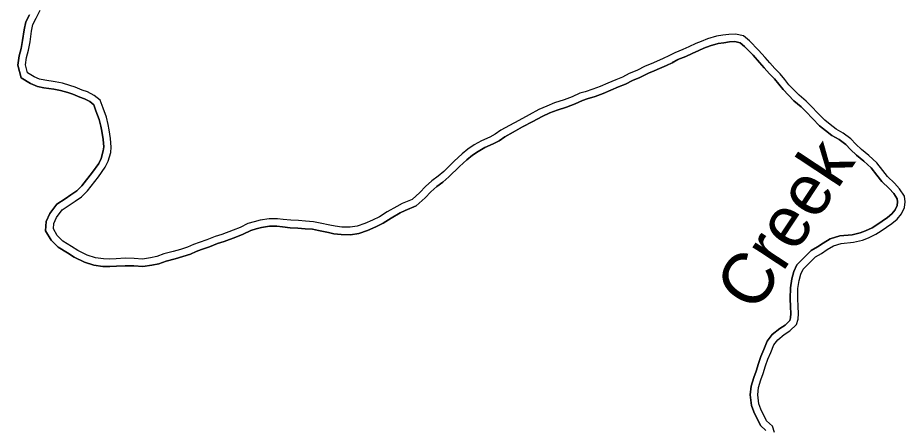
# Model space of a CAD drawing. Extents: x -29.6 to 34, y 0 to 22.
# Drawn here: x -24.699 to -23.161, y 8.694 to 9.402 of the extents above; entities that cross this region are included whole.
import ezdxf

# ---------------------------------------------------------------- set-up
doc = ezdxf.new("R2010")
doc.units = 0
doc.layers.add('GM_X_Major_River', color=7, linetype='Continuous')
doc.layers.add('GM_X_Major_River_Text', color=7, linetype='Continuous')

msp = doc.modelspace()

# ---------------------------------------------------------------- linework, layer by layer
at = {"layer": 'GM_X_Major_River'}
for points in [[(-24.5511, 9.2451), (-24.5561, 9.2589), (-24.5665, 9.2673), (-24.5779, 9.2736), (-24.5871, 9.2764), (-24.5992, 9.2813), (-24.6084, 9.2844), (-24.6215, 9.2883), (-24.634, 9.291), (-24.6517, 9.2934), (-24.6609, 9.2951), (-24.6705, 9.2993), (-24.6819, 9.3063), (-24.6855, 9.3201), (-24.6835, 9.3329), (-24.68, 9.3457), (-24.6776, 9.3603), (-24.6749, 9.3788), (-24.6725, 9.3902), (-24.6669, 9.4013), (-24.6603, 9.4148)], [(-24.5634, 9.2406), (-24.5672, 9.251), (-24.5738, 9.2565), (-24.583, 9.2615), (-24.5914, 9.2641), (-24.6037, 9.2691), (-24.6123, 9.272), (-24.6248, 9.2756), (-24.6362, 9.2781), (-24.6537, 9.2805), (-24.6648, 9.2825), (-24.6766, 9.2877), (-24.6932, 9.2979), (-24.6989, 9.3195), (-24.6963, 9.3357), (-24.6928, 9.3485), (-24.6906, 9.3623), (-24.6878, 9.3811), (-24.685, 9.3946), (-24.6786, 9.4071)], [(-24.6786, 9.4071), (-24.685, 9.3946), (-24.6878, 9.3811), (-24.6906, 9.3623), (-24.6928, 9.3485), (-24.6963, 9.3357), (-24.6989, 9.3195), (-24.6932, 9.2979), (-24.6766, 9.2877), (-24.6648, 9.2825), (-24.6537, 9.2805), (-24.6362, 9.2781), (-24.6248, 9.2756), (-24.6123, 9.272), (-24.6037, 9.2691), (-24.5914, 9.2641), (-24.583, 9.2615), (-24.5738, 9.2565), (-24.5672, 9.251), (-24.5634, 9.2407)], [(-23.3877, 8.6831), (-23.3909, 8.6941), (-23.4016, 8.7032), (-23.4113, 8.7238), (-23.4146, 8.733), (-23.4165, 8.7486), (-23.4151, 8.761), (-23.4113, 8.7745), (-23.4071, 8.7852), (-23.403, 8.7984), (-23.3991, 8.8102), (-23.3939, 8.8219), (-23.3887, 8.8348), (-23.382, 8.8437), (-23.3707, 8.8527), (-23.3609, 8.8591), (-23.3496, 8.8702), (-23.3468, 8.8795), (-23.3462, 8.8894), (-23.3466, 8.9015), (-23.3474, 8.9154), (-23.3472, 8.9328), (-23.3451, 8.9466), (-23.342, 8.9573), (-23.3378, 8.9662), (-23.3164, 8.9877), (-23.3061, 8.9935), (-23.2963, 9.0003), (-23.2857, 9.0068), (-23.2719, 9.0108), (-23.2506, 9.0127), (-23.2354, 9.0164), (-23.2248, 9.0204), (-23.2121, 9.0265), (-23.2029, 9.0323), (-23.1938, 9.0388), (-23.1842, 9.0452), (-23.1751, 9.0528), (-23.1677, 9.0621), (-23.1625, 9.0728), (-23.1611, 9.0827), (-23.1622, 9.0927), (-23.1708, 9.1054), (-23.1797, 9.1149), (-23.1919, 9.1269), (-23.2001, 9.1371), (-23.2105, 9.1505), (-23.224, 9.1629), (-23.2368, 9.1734), (-23.2468, 9.1829), (-23.2554, 9.1921), (-23.2689, 9.2016), (-23.281, 9.2086), (-23.291, 9.2167), (-23.3006, 9.2244), (-23.3124, 9.2364), (-23.3234, 9.248), (-23.3327, 9.2572), (-23.3452, 9.2678), (-23.3541, 9.2766), (-23.3626, 9.2857), (-23.3698, 9.2949), (-23.378, 9.3048), (-23.3869, 9.3136), (-23.3958, 9.3235), (-23.4037, 9.333), (-23.4151, 9.3457), (-23.4308, 9.3616), (-23.4415, 9.3704), (-23.455, 9.3735), (-23.4667, 9.373), (-23.4773, 9.3715), (-23.4879, 9.3697), (-23.5035, 9.3653), (-23.5148, 9.3609), (-23.524, 9.357), (-23.536, 9.3515), (-23.5462, 9.3468), (-23.5604, 9.341), (-23.571, 9.3356)], [(-23.5651, 9.3239), (-23.5549, 9.3292), (-23.541, 9.3349), (-23.5306, 9.3397), (-23.5187, 9.345), (-23.5099, 9.3488), (-23.4994, 9.3529), (-23.485, 9.3569), (-23.4753, 9.3586), (-23.4655, 9.36), (-23.4562, 9.3604), (-23.4474, 9.3583), (-23.4396, 9.3519), (-23.4246, 9.3368), (-23.4136, 9.3245), (-23.4057, 9.315), (-23.3964, 9.3046), (-23.3876, 9.296), (-23.38, 9.2867), (-23.3726, 9.2773), (-23.3634, 9.2675), (-23.354, 9.2581), (-23.3415, 9.2476), (-23.3327, 9.2389), (-23.3218, 9.2273), (-23.3094, 9.2147), (-23.2992, 9.2065), (-23.2884, 9.1978), (-23.2759, 9.1906), (-23.264, 9.1822), (-23.2561, 9.1737), (-23.2455, 9.1636), (-23.2326, 9.153), (-23.2201, 9.1416), (-23.2104, 9.129), (-23.2016, 9.1181), (-23.1891, 9.1058), (-23.1811, 9.0972), (-23.1749, 9.088), (-23.1743, 9.0828), (-23.1751, 9.0766), (-23.1788, 9.0691), (-23.1844, 9.062), (-23.1921, 9.0557), (-23.2012, 9.0495), (-23.2102, 9.0432), (-23.2184, 9.038), (-23.23, 9.0324), (-23.2393, 9.0289), (-23.2528, 9.0257), (-23.2743, 9.0237), (-23.291, 9.0188), (-23.3034, 9.0112), (-23.3131, 9.0046), (-23.3243, 8.9982), (-23.3487, 8.9738), (-23.3543, 8.9619), (-23.3579, 8.9494), (-23.3602, 8.9338), (-23.3605, 8.9151), (-23.3597, 8.9009), (-23.3593, 8.8896), (-23.3598, 8.8818), (-23.3611, 8.8772), (-23.3691, 8.8693), (-23.3784, 8.8632), (-23.3915, 8.8529), (-23.4001, 8.8412), (-23.4059, 8.827), (-23.4114, 8.8148), (-23.4154, 8.8024), (-23.4194, 8.7896), (-23.4237, 8.7787), (-23.428, 8.7635), (-23.4296, 8.7485), (-23.4274, 8.73), (-23.4234, 8.7188), (-23.4122, 8.6951), (-23.4024, 8.6867)], [(-23.4024, 8.6867), (-23.4122, 8.6951), (-23.4234, 8.7188), (-23.4274, 8.73), (-23.4296, 8.7485), (-23.428, 8.7635), (-23.4237, 8.7787), (-23.4194, 8.7896), (-23.4154, 8.8024), (-23.4114, 8.8148), (-23.4059, 8.827), (-23.4001, 8.8412), (-23.3915, 8.8529), (-23.3784, 8.8632), (-23.3691, 8.8693), (-23.3611, 8.8772), (-23.3598, 8.8818), (-23.3593, 8.8896), (-23.3597, 8.9009), (-23.3605, 8.9151), (-23.3602, 8.9338), (-23.3579, 8.9494), (-23.3543, 8.9619), (-23.3487, 8.9738), (-23.3243, 8.9982), (-23.3131, 9.0046), (-23.3034, 9.0112), (-23.291, 9.0188), (-23.2743, 9.0237), (-23.2528, 9.0257), (-23.2393, 9.0289), (-23.23, 9.0324), (-23.2184, 9.038), (-23.2102, 9.0432), (-23.2012, 9.0495), (-23.1921, 9.0557), (-23.1844, 9.062), (-23.1788, 9.0691), (-23.1751, 9.0766), (-23.1743, 9.0828), (-23.1749, 9.088), (-23.1811, 9.0972), (-23.1891, 9.1058), (-23.2016, 9.1181), (-23.2104, 9.129), (-23.2201, 9.1416), (-23.2326, 9.153), (-23.2455, 9.1636), (-23.2561, 9.1737), (-23.264, 9.1822), (-23.2759, 9.1906), (-23.2884, 9.1978), (-23.2992, 9.2065), (-23.3094, 9.2147), (-23.3218, 9.2273), (-23.3327, 9.2389), (-23.3415, 9.2476), (-23.354, 9.2581), (-23.3634, 9.2675), (-23.3726, 9.2773), (-23.38, 9.2867), (-23.3876, 9.296), (-23.3964, 9.3046), (-23.4057, 9.315), (-23.4136, 9.3245), (-23.4246, 9.3368), (-23.4396, 9.3519), (-23.4474, 9.3583), (-23.4562, 9.3604), (-23.4655, 9.36), (-23.4753, 9.3586), (-23.485, 9.3569), (-23.4994, 9.3529), (-23.5099, 9.3488), (-23.5187, 9.345), (-23.5306, 9.3397), (-23.541, 9.3349), (-23.5549, 9.3292), (-23.565, 9.324)], [(-23.571, 9.3356), (-23.5805, 9.3309), (-23.5921, 9.3259), (-23.6013, 9.3219), (-23.6116, 9.3176), (-23.6264, 9.3104), (-23.6395, 9.3049), (-23.6511, 9.2988), (-23.6628, 9.2941), (-23.6762, 9.2883), (-23.6896, 9.2829), (-23.7027, 9.2778), (-23.7158, 9.2735), (-23.725, 9.2709), (-23.7381, 9.2648), (-23.7522, 9.2593), (-23.7688, 9.2542), (-23.7822, 9.2488), (-23.796, 9.2427), (-23.8126, 9.2337), (-23.8306, 9.2239), (-23.8469, 9.2149), (-23.8617, 9.2067), (-23.8716, 9.1998), (-23.8811, 9.1951), (-23.8956, 9.1883), (-23.9079, 9.1815), (-23.9189, 9.1739), (-23.9291, 9.1657), (-23.9425, 9.1535), (-23.9604, 9.1356), (-23.9706, 9.1274), (-23.9812, 9.1191), (-23.9921, 9.1094), (-24.002, 9.0991), (-24.0154, 9.0869), (-24.033, 9.0797), (-24.0422, 9.075), (-24.0588, 9.0656), (-24.0719, 9.057), (-24.0842, 9.0512), (-24.0976, 9.0451), (-24.1107, 9.0407), (-24.1231, 9.0389), (-24.1376, 9.0391), (-24.149, 9.0405), (-24.1582, 9.0422), (-24.1749, 9.0456), (-24.1862, 9.0484), (-24.2001, 9.0493), (-24.2125, 9.0503), (-24.2259, 9.0509), (-24.2387, 9.0523), (-24.249, 9.0536), (-24.2635, 9.0535), (-24.2791, 9.0513), (-24.2894, 9.0483), (-24.3, 9.0454), (-24.3134, 9.0386), (-24.3258, 9.0339), (-24.3452, 9.0263), (-24.3569, 9.023), (-24.371, 9.0169), (-24.3848, 9.0125), (-24.3943, 9.0089), (-24.4046, 9.0045), (-24.4166, 9.0002), (-24.4293, 8.9966), (-24.4456, 8.9925), (-24.458, 8.9882), (-24.4689, 8.986), (-24.4827, 8.9837), (-24.4969, 8.9847), (-24.5129, 8.985), (-24.5284, 8.9841), (-24.5394, 8.9837), (-24.5504, 8.984), (-24.5639, 8.986), (-24.5784, 8.9905), (-24.5948, 8.9982), (-24.6055, 9.0053), (-24.6208, 9.0144), (-24.6304, 9.0243), (-24.6372, 9.0359), (-24.6366, 9.0452), (-24.6317, 9.0559), (-24.6218, 9.0691), (-24.6095, 9.077), (-24.5993, 9.0842), (-24.5883, 9.0917), (-24.5781, 9.1017), (-24.5588, 9.1264), (-24.5472, 9.1428), (-24.542, 9.1535), (-24.5378, 9.1684), (-24.5368, 9.1777), (-24.538, 9.1926), (-24.5402, 9.2075), (-24.542, 9.2167), (-24.5453, 9.2295), (-24.5511, 9.2451)], [(-23.5652, 9.3239), (-23.575, 9.3191), (-23.587, 9.3139), (-23.5962, 9.3099), (-23.6062, 9.3057), (-23.6211, 9.2984), (-23.6339, 9.2931), (-23.6456, 9.2869), (-23.6578, 9.282), (-23.6712, 9.2763), (-23.6848, 9.2707), (-23.6983, 9.2655), (-23.712, 9.261), (-23.7204, 9.2586), (-23.7329, 9.2527), (-23.7479, 9.247), (-23.7645, 9.2419), (-23.7771, 9.2368), (-23.7902, 9.2309), (-23.8064, 9.2222), (-23.8244, 9.2125), (-23.8405, 9.2035), (-23.8548, 9.1956), (-23.8649, 9.1885), (-23.8754, 9.1834), (-23.8896, 9.1767), (-23.9011, 9.1703), (-23.9111, 9.1634), (-23.9206, 9.1558), (-23.9335, 9.144), (-23.9517, 9.1259), (-23.9625, 9.1171), (-23.9729, 9.1091), (-23.9831, 9.1), (-23.9928, 9.0897), (-24.0083, 9.0757), (-24.0276, 9.0678), (-24.036, 9.0635), (-24.052, 9.0545), (-24.0655, 9.0456), (-24.0787, 9.0394), (-24.0929, 9.0329), (-24.1077, 9.028), (-24.1223, 9.0258), (-24.1385, 9.0261), (-24.151, 9.0276), (-24.1607, 9.0294), (-24.1778, 9.0329), (-24.1883, 9.0354), (-24.201, 9.0363), (-24.2133, 9.0373), (-24.2269, 9.0379), (-24.2402, 9.0393), (-24.2498, 9.0405), (-24.2625, 9.0405), (-24.2764, 9.0385), (-24.2858, 9.0358), (-24.2952, 9.0332), (-24.3081, 9.0266), (-24.3211, 9.0217), (-24.341, 9.0139), (-24.3525, 9.0107), (-24.3664, 9.0046), (-24.3805, 9.0002), (-24.3895, 8.9968), (-24.3998, 8.9924), (-24.4126, 8.9878), (-24.426, 8.9839), (-24.4418, 8.98), (-24.4545, 8.9756), (-24.4666, 8.9731), (-24.4821, 8.9706), (-24.4975, 8.9717), (-24.5126, 8.9719), (-24.5278, 8.9711), (-24.5393, 8.9706), (-24.5516, 8.9709), (-24.5668, 8.9732), (-24.5832, 8.9783), (-24.6012, 8.9868), (-24.6124, 8.9942), (-24.6289, 9.004), (-24.6409, 9.0163), (-24.6505, 9.0328), (-24.6494, 9.0485), (-24.643, 9.0626), (-24.6309, 9.0788), (-24.6168, 9.0878), (-24.6067, 9.0949), (-24.5967, 9.1018), (-24.5879, 9.1104), (-24.5693, 9.1342), (-24.5585, 9.1495), (-24.5542, 9.1581), (-24.5507, 9.1709), (-24.5499, 9.1779), (-24.551, 9.1911), (-24.5531, 9.2052), (-24.5548, 9.2138), (-24.5578, 9.2256), (-24.5633, 9.2405)], [(-24.5634, 9.2407), (-24.5578, 9.2256), (-24.5548, 9.2138), (-24.5531, 9.2052), (-24.551, 9.1911), (-24.5499, 9.1779), (-24.5507, 9.1709), (-24.5542, 9.1581), (-24.5585, 9.1495), (-24.5693, 9.1342), (-24.5879, 9.1104), (-24.5967, 9.1018), (-24.6067, 9.0949), (-24.6168, 9.0878), (-24.6309, 9.0788), (-24.643, 9.0626), (-24.6494, 9.0485), (-24.6505, 9.0328), (-24.6409, 9.0163), (-24.6289, 9.004), (-24.6124, 8.9942), (-24.6012, 8.9868), (-24.5832, 8.9783), (-24.5668, 8.9732), (-24.5516, 8.9709), (-24.5393, 8.9706), (-24.5278, 8.9711), (-24.5126, 8.9719), (-24.4975, 8.9717), (-24.4821, 8.9706), (-24.4666, 8.9731), (-24.4545, 8.9756), (-24.4418, 8.98), (-24.426, 8.9839), (-24.4126, 8.9878), (-24.3998, 8.9924), (-24.3895, 8.9968), (-24.3805, 9.0002), (-24.3664, 9.0046), (-24.3525, 9.0107), (-24.341, 9.0139), (-24.3211, 9.0217), (-24.3081, 9.0266), (-24.2952, 9.0332), (-24.2858, 9.0358), (-24.2764, 9.0385), (-24.2625, 9.0405), (-24.2498, 9.0405), (-24.2402, 9.0393), (-24.2269, 9.0379), (-24.2133, 9.0373), (-24.201, 9.0363), (-24.1883, 9.0354), (-24.1778, 9.0329), (-24.1607, 9.0294), (-24.151, 9.0276), (-24.1385, 9.0261), (-24.1223, 9.0258), (-24.1077, 9.028), (-24.0929, 9.0329), (-24.0787, 9.0394), (-24.0655, 9.0456), (-24.052, 9.0545), (-24.036, 9.0635), (-24.0276, 9.0678), (-24.0083, 9.0757), (-23.9928, 9.0897), (-23.9831, 9.1), (-23.9729, 9.1091), (-23.9625, 9.1171), (-23.9517, 9.1259), (-23.9335, 9.144), (-23.9206, 9.1558), (-23.9111, 9.1634), (-23.9011, 9.1703), (-23.8896, 9.1767), (-23.8754, 9.1834), (-23.8649, 9.1885), (-23.8548, 9.1956), (-23.8405, 9.2035), (-23.8244, 9.2125), (-23.8064, 9.2222), (-23.7902, 9.2309), (-23.7771, 9.2368), (-23.7645, 9.2419), (-23.7479, 9.247), (-23.7329, 9.2527), (-23.7204, 9.2586), (-23.712, 9.261), (-23.6983, 9.2655), (-23.6848, 9.2707), (-23.6712, 9.2763), (-23.6578, 9.282), (-23.6456, 9.2869), (-23.6339, 9.2931), (-23.6211, 9.2984), (-23.6062, 9.3057), (-23.5962, 9.3099), (-23.587, 9.3139), (-23.575, 9.3191), (-23.5651, 9.3239)]]:
    msp.add_lwpolyline(points, dxfattribs=at)

# ---------------------------------------------------------------- texts
at = {"layer": 'GM_X_Major_River_Text'}
msp.add_text('Creek', height=0.0888, rotation=56.5714, dxfattribs=at).set_placement((-23.4207, 8.8882))

doc.saveas('drawing.dxf')
